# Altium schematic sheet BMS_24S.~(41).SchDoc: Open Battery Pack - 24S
size A3; Date: 26/03/2019; Author: Morgane Vallée - Samuel Lesueur; Revision: 1.0; SheetNumber: 3; SheetTotal: 5
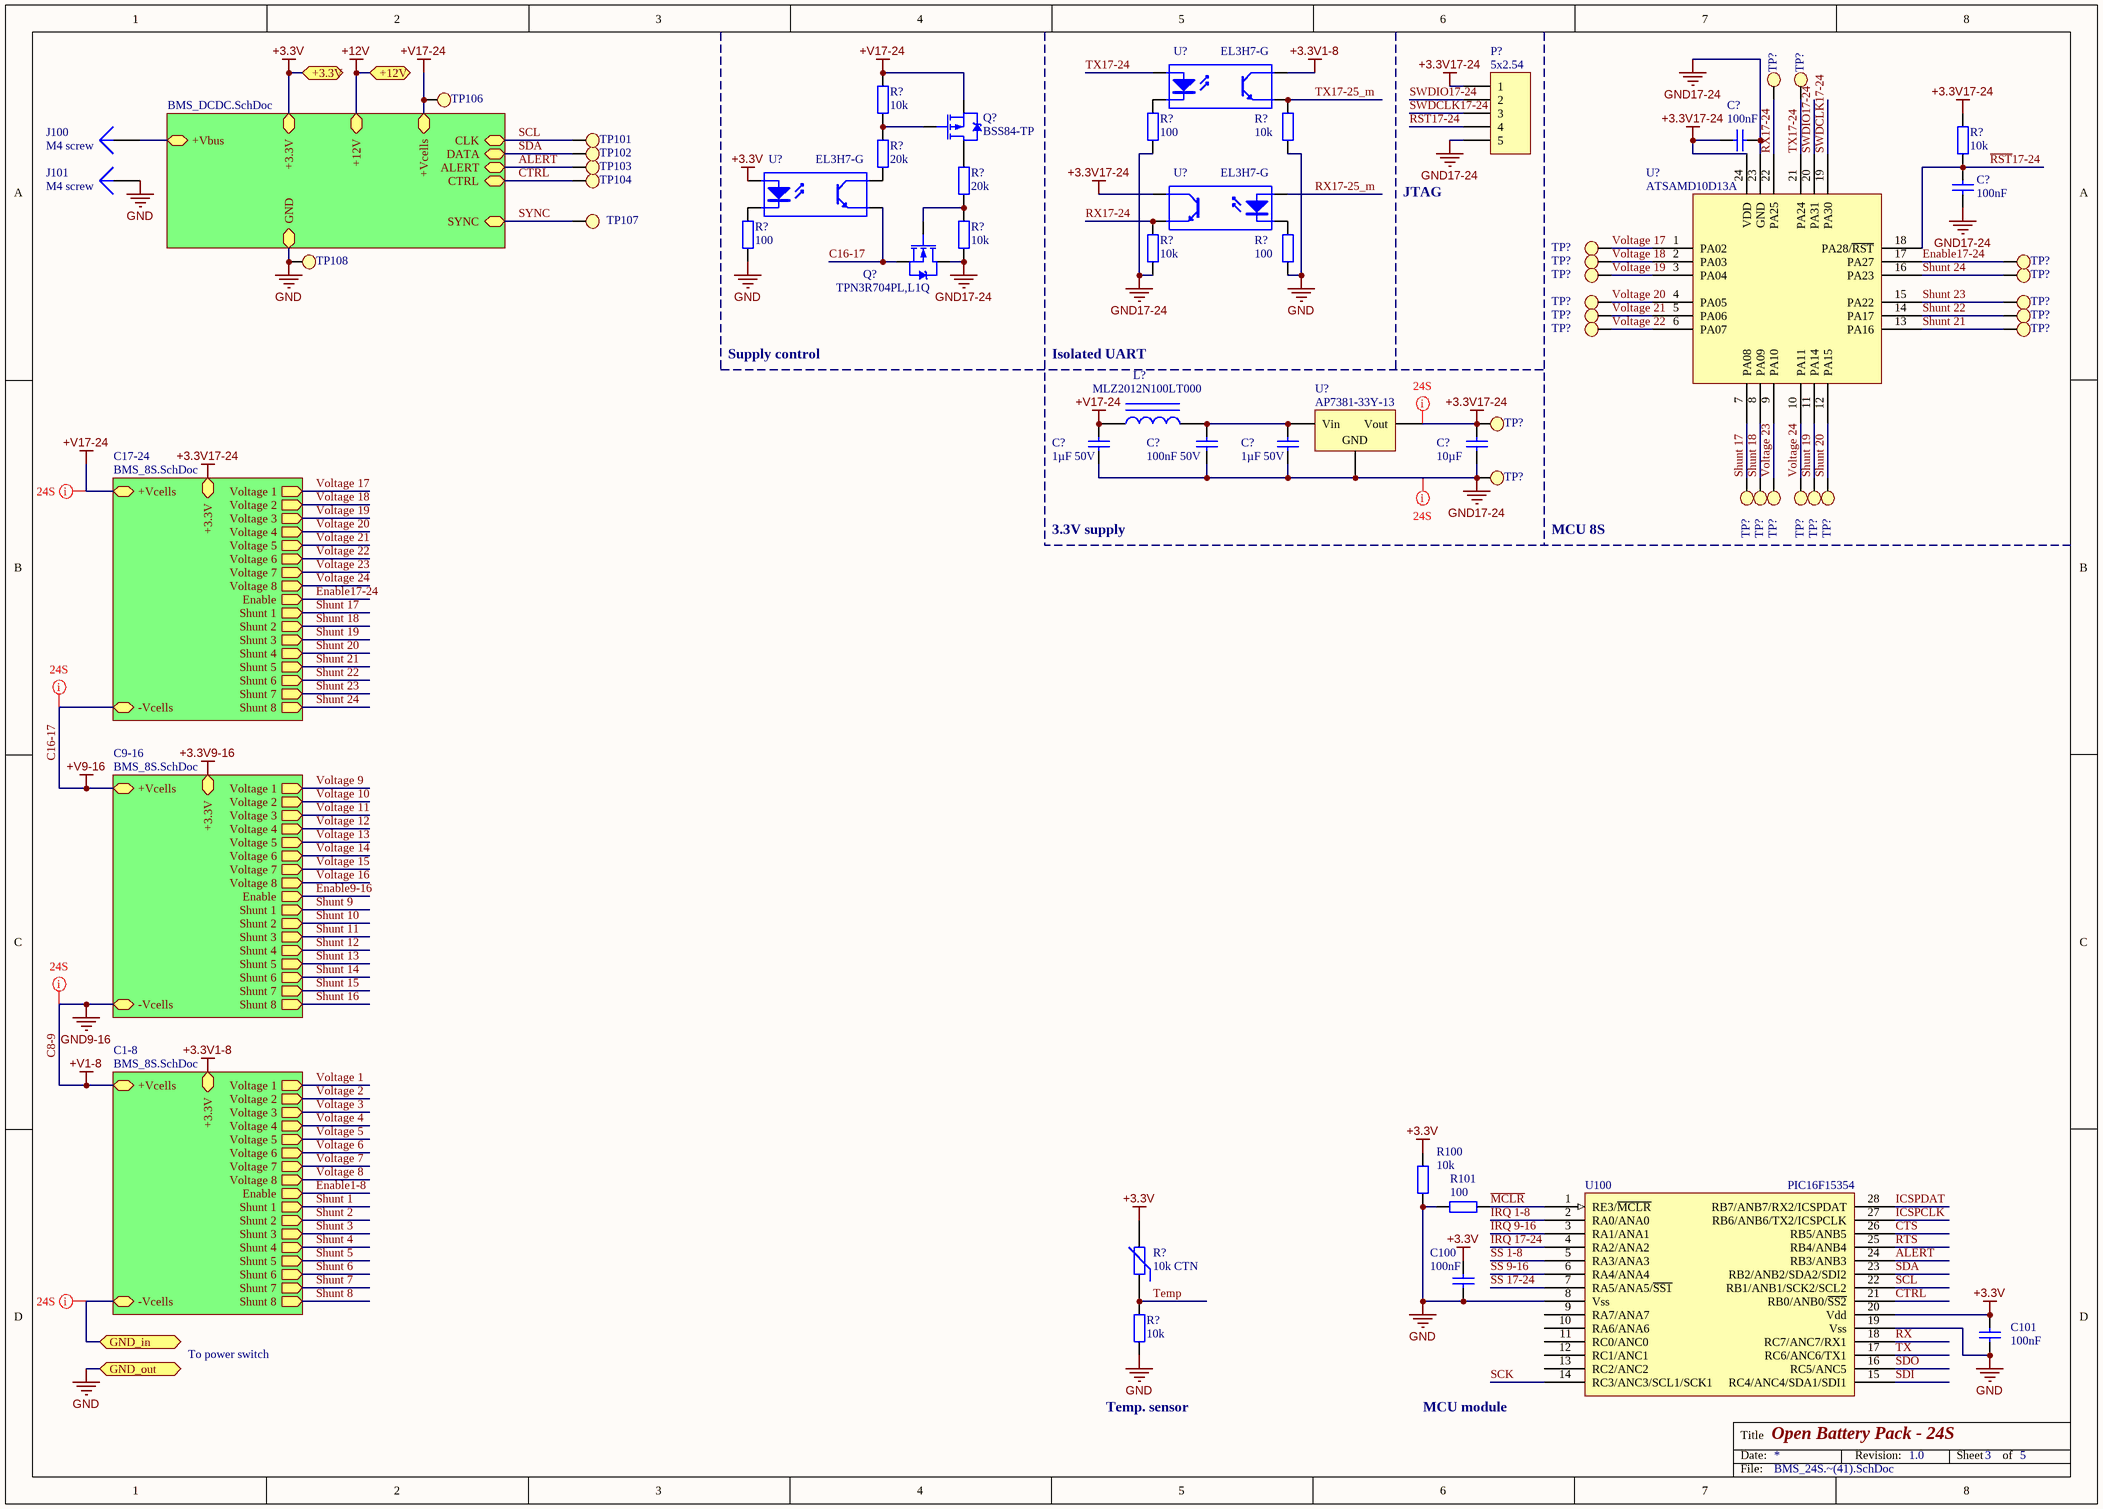
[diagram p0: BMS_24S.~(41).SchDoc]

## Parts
(Parts that share a designator on the sheet are numbered #1, #2 ... from top to bottom, then left to right.)
C100  100nF  [C0603]
C101  100nF  [C0603]
C?#1  100nF  [C0603]
C?#2  100nF  [C0603]
C?#3  1µF 50V  [C0805]
C?#4  100nF 50V  [C0603]
C?#5  1µF 50V  [C0805]
C?#6  10µF  [C0603]
J100  M4 screw  [HOLE_4]
J101  M4 screw  [HOLE_4]
L?  MLZ2012N100LT000  [FER 0805/2012]
P?  5x2.54  [HDR1X5]
Q?#1  BSS84-TP  [DIODES SOT-23-3]
Q?#2  TPN3R704PL,L1Q  [DIODES SOT-23-3]
R100  10k  [R0603]
R101  100  [R0603]
R?#1  10k  [R0603]
R?#2  10k  [R0603]
R?#3  100  [R0603]
R?#4  10k  [R0603]
R?#5  20k  [R0603]
R?#6  20k  [R0603]
R?#7  100  [R0603]
R?#8  100  [R0603]
R?#9  10k  [R0603]
R?#10  10k  [R0603]
R?#11  10k CTN  [NTC 0402/1005]
R?#12  10k  [R0603]
TP101  Test Point  [Test Point]  (value not drawn)
TP102  Test Point  [Test Point]  (value not drawn)
TP103  Test Point  [Test Point]  (value not drawn)
TP104  Test Point  [Test Point]  (value not drawn)
TP106  Test Point  [Test Point]  (value not drawn)
TP107  Test Point  [Test Point]  (value not drawn)
TP108  Test Point  [Test Point]  (value not drawn)
TP?#1  Test Point  [Test Point]  (value not drawn)
TP?#2  Test Point  [Test Point]  (value not drawn)
TP?#3  Test Point  [Test Point]  (value not drawn)
TP?#4  Test Point  [Test Point]  (value not drawn)
TP?#5  Test Point  [Test Point]  (value not drawn)
TP?#6  Test Point  [Test Point]  (value not drawn)
TP?#7  Test Point  [Test Point]  (value not drawn)
TP?#8  Test Point  [Test Point]  (value not drawn)
TP?#9  Test Point  [Test Point]  (value not drawn)
TP?#10  Test Point  [Test Point]  (value not drawn)
TP?#11  Test Point  [Test Point]  (value not drawn)
TP?#12  Test Point  [Test Point]  (value not drawn)
TP?#13  Test Point  [Test Point]  (value not drawn)
TP?#14  Test Point  [Test Point]  (value not drawn)
TP?#15  Test Point  [Test Point]  (value not drawn)
TP?#16  Test Point  [Test Point]  (value not drawn)
TP?#17  Test Point  [Test Point]  (value not drawn)
TP?#18  Test Point  [Test Point]  (value not drawn)
TP?#19  Test Point  [Test Point]  (value not drawn)
TP?#20  Test Point  [Test Point]  (value not drawn)
TP?#21  Test Point  [Test Point]  (value not drawn)
U100  PIC16F15354  [SSOP_28]
U?#1  EL3H7-G  [OPTO_EL3H7-G]
U?#2  EL3H7-G  [OPTO_EL3H7-G]
U?#3  EL3H7-G  [OPTO_EL3H7-G]
U?#4  ATSAMD10D13A  [SMSC QFN-24 4x4MM]
U?#5  AP7381-33Y-13  [ST SOIC-8N]

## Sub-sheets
C1-8 = BMS_8S.SchDoc: Voltage 6 (out), Shunt 2 (out), Shunt 7 (out), Shunt 6 (out), Voltage 3 (out), Voltage 5 (out), Shunt 8 (out), Voltage 8 (out), Voltage 7 (out), +3.3V, Voltage 2 (out), Shunt 4 (out), Shunt 3 (out), Shunt 5 (out), Voltage 4 (out), -Vcells, +Vcells, Shunt 1 (out), Voltage 1 (out), Enable (out)
C9-16 = BMS_8S.SchDoc: Voltage 6 (out), Shunt 2 (out), Shunt 7 (out), Shunt 6 (out), Voltage 3 (out), Voltage 5 (out), Shunt 8 (out), Voltage 8 (out), Voltage 7 (out), +3.3V, Voltage 2 (out), Shunt 4 (out), Shunt 3 (out), Shunt 5 (out), Voltage 4 (out), -Vcells, +Vcells, Shunt 1 (out), Voltage 1 (out), Enable (out)
C17-24 = BMS_8S.SchDoc: Voltage 6 (out), Shunt 2 (out), Shunt 7 (out), Shunt 6 (out), Voltage 3 (out), Voltage 5 (out), Shunt 8 (out), Voltage 8 (out), Voltage 7 (out), +3.3V, Voltage 2 (out), Shunt 4 (out), Shunt 3 (out), Shunt 5 (out), Voltage 4 (out), -Vcells, +Vcells, Shunt 1 (out), Voltage 1 (out), Enable (out)
? = BMS_DCDC.SchDoc: CTRL (bidir), SYNC (bidir), CLK (bidir), DATA (bidir), ALERT (bidir), GND, +3.3V, +Vbus, +Vcells, +12V

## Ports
+3.3V, +12V, GND_in, GND_out

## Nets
+3.3V: C100.2 C101.2 R100.2 R?#11.2 U100.20(Vdd) U?#2.1(A) ; port +3.3V, sheet /+3.3V
+3.3V1-8: U?#1.4(C) ; sheet C1-8/+3.3V
+3.3V17-24: C?#1.2 C?#6.1 P?.1 R?#4.2 TP?#14.1 U?#3.4(C) U?#4.24(VDD) U?#5.3(Vout) ; sheet C17-24/+3.3V
+12V: port +12V, sheet /+12V
+V17-24: C?#3.1 L?.1 Q?#1.2(S) R?#1.2 TP106.1 ; sheet /+Vcells, sheet C17-24/+Vcells
C8-9: sheet C1-8/+Vcells, sheet C9-16/-Vcells  [also labelled +V1-8, GND9-16]
C16-17: Q?#2.2(S) U?#2.3(E) ; sheet C9-16/+Vcells, sheet C17-24/-Vcells  [also labelled +V9-16]
GND: C100.1 C101.1 J101.1 R100.1 R101.2 R?#2.2 R?#7.2 R?#8.1 R?#12.2 TP108.1 U100.8(Vss) U100.19(Vss) ; port GND_out, sheet /GND
GND17-24: C?#1.1 C?#2.1 C?#3.2 C?#4.2 C?#5.2 C?#6.2 P?.5 Q?#2.3(D) R?#3.1 R?#9.1 R?#10.1 TP?#15.1 U?#4.23(GND) U?#5.2(GND)
ALERT: TP103.1 U100.24(RB3/ANB3) ; sheet /ALERT
CTRL: TP104.1 U100.21(RB0/ANB0/~{SS2}) ; sheet /CTRL
CTS: U100.26(RB5/ANB5)
Enable17-24: TP?#5.1 U?#4.17(PA27) ; sheet C17-24/Enable
GND_in: port GND_in, sheet C1-8/-Vcells
ICSPCLK: U100.27(RB6/ANB6/TX2/ICSPCLK)
ICSPDAT: U100.28(RB7/ANB7/RX2/ICSPDAT)
IRQ 1-8: U100.2(RA0/ANA0)
IRQ 9-16: U100.3(RA1/ANA1)
IRQ 17-24: U100.4(RA2/ANA2)
~{MCLR}: R101.1 U100.1(RE3/~{MCLR})
~{RST}17-24: C?#2.2 P?.4 R?#4.1 U?#4.18(PA28/~{RST})
RTS: U100.25(RB4/ANB4)
RX: U100.18(RC7/ANC7/RX1)
RX17-24: R?#10.2 TP?#1.1 U?#3.3(E) U?#4.22(PA25)
RX17-25_m: U?#3.1(A)
~{SS} 1-8: U100.5(RA3/ANA3)
~{SS} 9-16: U100.6(RA4/ANA4)
~{SS} 17-24: U100.7(RA5/ANA5/~{SS1})
SCK: U100.14(RC3/ANC3/SCL1/SCK1)
SCL: TP101.1 U100.22(RB1/ANB1/SCK2/SCL2) ; sheet /CLK
SDA: TP102.1 U100.23(RB2/ANB2/SDA2/SDI2) ; sheet /DATA
SDI: U100.15(RC4/ANC4/SDA1/SDI1)
SDO: U100.16(RC5/ANC5)
Shunt 17: TP?#16.1 U?#4.7(PA08) ; sheet C17-24/Shunt 1
Shunt 18: TP?#17.1 U?#4.8(PA09) ; sheet C17-24/Shunt 2
Shunt 19: TP?#20.1 U?#4.11(PA14) ; sheet C17-24/Shunt 3
Shunt 20: TP?#21.1 U?#4.12(PA15) ; sheet C17-24/Shunt 4
Shunt 21: TP?#13.1 U?#4.13(PA16) ; sheet C17-24/Shunt 5
Shunt 22: TP?#11.1 U?#4.14(PA17) ; sheet C17-24/Shunt 6
Shunt 23: TP?#9.1 U?#4.15(PA22) ; sheet C17-24/Shunt 7
Shunt 24: TP?#7.1 U?#4.16(PA23) ; sheet C17-24/Shunt 8
SWDCLK17-24: P?.3 U?#4.19(PA30)
SWDIO17-24: P?.2 U?#4.20(PA31)
SYNC: TP107.1 ; sheet /SYNC
Temp: R?#11.1 R?#12.1
TX: U100.17(RC6/ANC6/TX1)
TX17-24: TP?#2.1 U?#1.1(A) U?#4.21(PA24)
TX17-25_m: R?#2.1 U?#1.3(E)
Voltage 17: TP?#3.1 U?#4.1(PA02) ; sheet C17-24/Voltage 1
Voltage 18: TP?#4.1 U?#4.2(PA03) ; sheet C17-24/Voltage 2
Voltage 19: TP?#6.1 U?#4.3(PA04) ; sheet C17-24/Voltage 3
Voltage 20: TP?#8.1 U?#4.4(PA05) ; sheet C17-24/Voltage 4
Voltage 21: TP?#10.1 U?#4.5(PA06) ; sheet C17-24/Voltage 5
Voltage 22: TP?#12.1 U?#4.6(PA07) ; sheet C17-24/Voltage 6
Voltage 23: TP?#18.1 U?#4.9(PA10) ; sheet C17-24/Voltage 7
Voltage 24: TP?#19.1 U?#4.10(PA11) ; sheet C17-24/Voltage 8
NetC?#4_1: C?#4.1 C?#5.1 L?.2 U?#5.1(Vin)
NetJ100_1: J100.1 ; sheet /+Vbus
NetQ?#1_1: Q?#1.1(G) R?#1.1 R?#5.2
NetQ?#1_3: Q?#1.3(D) R?#6.2
NetQ?#2_1: Q?#2.1(G) R?#6.1 R?#9.2
NetR?#3_2: R?#3.2 U?#1.2(K)
NetR?#5_1: R?#5.1 U?#2.4(C)
NetR?#7_1: R?#7.1 U?#3.2(K)
NetR?#8_2: R?#8.2 U?#2.2(K)

Not connected (* = marked no-connect by the designer): U100 9(RA7/ANA7) 10(RA6/ANA6) 11(RC0/ANC0) 12(RC1/ANC1) 13(RC2/ANC2)

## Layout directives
net class 24S: +3.3V17-24, +V17-24, C8-9, C16-17, GND17-24, GND_in

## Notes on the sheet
- JTAG
- Supply control
- Isolated UART
- 3.3V supply
- MCU 8S
- To power switch
- Temp. sensor
- MCU module

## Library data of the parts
C100 C101 C?#1-C?#6 = Cap: Capacitor
J100 J101 = Plug
L? = Inductor Iron: Magnetic-Core Inductor
P? = Header 5: Header, 5-Pin
Q?#1 = MOSFET_P
Q?#2 = MOSFET_N
R100 R101 R?#1-R?#10 R?#12 = Res2: Resistor
R?#11 = Res Varistor: Varistor (Voltage-Sensitive Resistor)
U?#1-U?#3 = Optoisolator1: 4-Pin Phototransistor Optocoupler
U?#5 = Volt Reg: Voltage Regulator; pin to pad: 1>8 2>2+3+6+7 3>1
